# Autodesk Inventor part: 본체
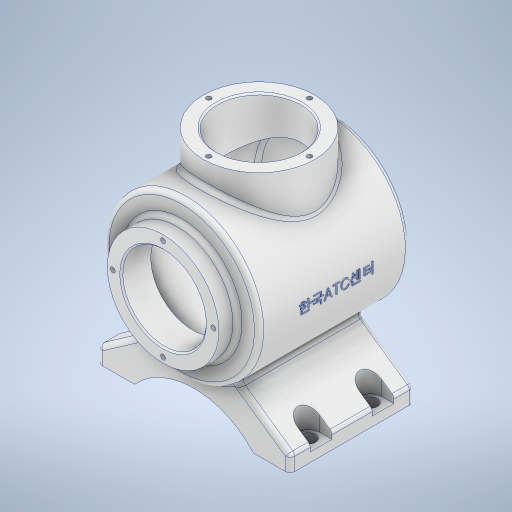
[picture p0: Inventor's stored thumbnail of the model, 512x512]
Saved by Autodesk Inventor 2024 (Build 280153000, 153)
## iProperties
Created: 2023-08
Part Number: 본체
Material: 알루미늄 6061
Document SubType Name: Modeling
Designer: Owner
Density: 2.7 g/cm^3
Appearance: 알루미늄 - 평지
Mass: 1296.71 g
Surface Area: 1060.44 cm^2
Volume: 480.264 cm^3
Author: Owner
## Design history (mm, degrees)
sketch "스케치1"
  geometry: L1 (36, 62)-(36, 50); L2 (36, 50)-(50, 50); L3 (50, 50)-(50, -46.336); L4 (0, 62)-(0, -58); L5 (43, -41.887)-(43, 43); L6 (43, 43)-(27, 43); L7 (27, 43)-(27, 62); L8 (36, 62)-(27, 62); A1 r 113 centre (0, 55) between (0, -58) and (50, -46.336); A2 r 106 centre (0, 55) between (0, -51) and (43, -41.887); 1 further point
  constraints: 16 end point, 4 perpendicular, 4 point on circle, 2 centre point, 2 point on line, 2 vertical, 1 horizontal, 1 horizontal alignment, 1 vertical alignment
  dimensions: "d0" = 120 vertical distance of L4.end L1.start; "d1" = 108 vertical distance of L4.end L2.end; "d2" = 113 radius of A1; "d3" = 100 diameter of L3 L4; "d4" = 72 diameter of L1 L4; "d5" = 62 distance of L4.start point (0, 0); "d6" = 7 radial gap between concentric circles of A1 A2; "d7" = 86 diameter of L5 L4; "d8" = 54 diameter of L7 L4; "d9" = 19 distance of L6.end L7.end
revolve "회전1" sketch "스케치1" stored, may be unused: angle "d10" = 90 deg
sketch "스케치2"
  geometry: L1 (62, -77)-(62, -67); L2 (62, -67)-(26.694, -42.278); L3 (-62, -77)-(-62, -67); L4 (-62, -67)-(-26.694, -42.278); L5 (-62, -77)-(-38.5, -77); L6 (38.5, -77)-(62, -77); A1 r 50 centre (0, 0) between (26.694, -42.278) and (-26.694, -42.278) reference; A2 r 52.096 centre (0, -112.096) between (38.5, -77) and (-38.5, -77); 2 further points
  constraints: 12 end point, 5 point on circle, 3 equal length, 2 horizontal, 2 horizontal alignment, 2 perpendicular, 1 centre point, 1 vertical, 1 vertical alignment
  dimensions: "d11" = 10 distance of L1.start L1.end; "d12" = 77 vertical distance of L1.start point (0, 0); "d13" = 55 deg angle of L2 L1; "d15" = 17 distance from line of point (0, -60) L6; "d16" = 77 distance of L6.start L5.end; "d17" = 124 distance between parallel lines of L1 L3
extrude "돌출1" join sketch "스케치2" distance "d18" = 42; taper "d19" = 0 deg; dims "d69" = 38, "d70" = 0
sketch "스케치3"
  geometry: L1 (-100.5, -80)-(-100.5, 0) reference; L2 (-100.5, 0)-(-77, 0) reference; C1 r 4.5 at (-92.5, -20); 1 further point
  constraints: 1 centre point
  dimensions: "d20" = 9 diameter of C1; "d21" = 8 distance from line of C1.centre L1; "d22" = 20 distance from line of C1.centre L2
extrude "돌출2" cut sketch "스케치3" stored distance "d23" = 0; taper "d24" = 0 deg
node "작업 평면1"
sketch "스케치4"
  geometry: L1 (-10.193, -20)-(8, -20); L2 (0, -27)-(8, -27); L3 (8, -13)-(0, -13); L4 (0, -80)-(0, 0) reference; L5 (0, 0)-(23.5, 0) reference; C1 r 4.5 at (8, -20) reference; A1 r 7 centre (8, -20) between (8, -27) and (8, -13); 2 further points
  constraints: 8 end point, 2 parallel, 2 point on circle, 2 point on line, 2 tangent, 1 centre point, 1 coincident, 1 horizontal, 1 midpoint
  dimensions: "d26" = 7 radius of A1
extrude "돌출3" cut sketch "스케치4" stored distance "d27" = 10; taper "d28" = 0 deg
node "작업 평면5"
sketch "스케치5"
  geometry: 2 further points
  constraints: 1 vertical alignment
  dimensions: "d29" = 32.5 distance of point (0, 0) point (0, 32.5)
hole "구멍1" sketch "스케치5" at (0, 32.5) diameter "d30" = 3.242; stored, may be unused: countersink angle "d34" = 90 deg, drill point angle "d36" = 118 deg; dims "d31" = 8, "d32" = 4, "d33" = 2, "d35" = 10
node "작업 평면2"
sketch "스케치6"
  geometry: C1 r 36 at (0, 0); 1 further point
  constraints: 1 centre point, 1 coincident
  dimensions: "d41" = 72 diameter of C1
extrude "돌출4" join sketch "스케치6" stored distance "d42" = 10; taper "d43" = 0 deg
sketch "스케치7"
  geometry: C1 r 27 at (0, 0); 1 further point
  constraints: 1 centre point, 1 coincident
  dimensions: "d44" = 54 diameter of C1
extrude "돌출5" cut sketch "스케치7" stored distance "d45" = 10; taper "d46" = 0 deg
sketch "스케치8"
  geometry: 2 further points
  constraints: 1 horizontal alignment
  dimensions: "d47" = 32.5 distance of point (0, 0) point (-32.5, 0)
hole "구멍2" sketch "스케치8" at (-32.5, 0) diameter "d48" = 3.242; stored, may be unused: countersink angle "d52" = 90 deg, drill point angle "d54" = 118 deg; dims "d49" = 8, "d50" = 4, "d51" = 2, "d53" = 10
node "작업 평면3"
sketch "스케치9"
  geometry: L1 (-36, 60.168)-(36, 60.168) reference; 2 further points
  constraints: 1 coincident, 1 other
feature "엠보싱1" sketch "스케치9" dims "d0" = 120, "d1" = 108, "d2" = 113, "d3" = 100, "d4" = 72, "d5" = 62, "d6" = 7, "d7" = 86, "d8" = 54, "d9" = 19, "d12" = 77, "d59" = 0.5, "d60" = 0
fillet "모깎기1" dims "d61" = 3
chamfer "모따기1" distance "d62" = 1; stored, may be unused: second distance "d63" = 2, angle "d64" = 45 deg
fillet "모깎기2" dims "d65" = 3
fillet "모깎기3" dims "d66" = 3
fillet "모깎기4" dims "d67" = 3
fillet "모깎기6" dims "d71" = 3
node "솔리드1"
mirror "미러1"
mirror "미러2"
pattern_circular "원형 패턴1" dims angle "d38" = 360 deg
pattern_circular "원형 패턴2" dims angle "d56" = 360 deg
feature "A9D066F2-1C7D-4E18-AEED-F7BC21143FA4" dims "d30" = 3.242, "d31" = 8, "d32" = 4, "d33" = 2, "d34" = 90 deg, "d35" = 10, "d36" = 118 deg
other parameters: "d25" = -6, "d40" = 65
